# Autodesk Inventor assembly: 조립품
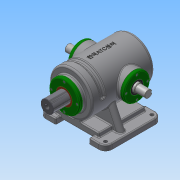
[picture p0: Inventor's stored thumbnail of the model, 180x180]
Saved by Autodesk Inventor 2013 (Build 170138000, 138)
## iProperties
Created: 2018-06
Part Number: 조립품
Document SubType Name: Assembly
Designer: Administrator
Mass: 8488.24 g
Surface Area: 4294.68 cm^2
Volume: 2307.11 cm^3
Density: 3.67917 g/cm^3
Author: Administrator
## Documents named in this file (13)
- C:\Users\Administrator\Desktop\380628V1014\조립품.iam
- C:\Users\Administrator\Desktop\380628V1014\본체.ipt
- C:\Users\Administrator\Desktop\380628V1014\가변 스프링.ipt
- C:\Users\Administrator\Desktop\380628V1014\베어링 6205.ipt
- 베어링 6205.ipt
- C:\Users\Administrator\Desktop\380628V1014\볼트 M4.ipt
- C:\Users\Administrator\Desktop\380628V1014\부시.ipt
- C:\Users\Administrator\Desktop\380628V1014\슬라이드 커버.ipt
- C:\Users\Administrator\Desktop\380628V1014\슬라이드.ipt
- C:\Users\Administrator\Desktop\380628V1014\오일실.ipt
- 오일실.ipt
- C:\Users\Administrator\Desktop\380628V1014\축 커버.ipt
- C:\Users\Administrator\Desktop\380628V1014\편심축.ipt
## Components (1 placed, 1 different names)
1. 가변 스프링:1
